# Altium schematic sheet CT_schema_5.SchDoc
size 304 x 172 mm
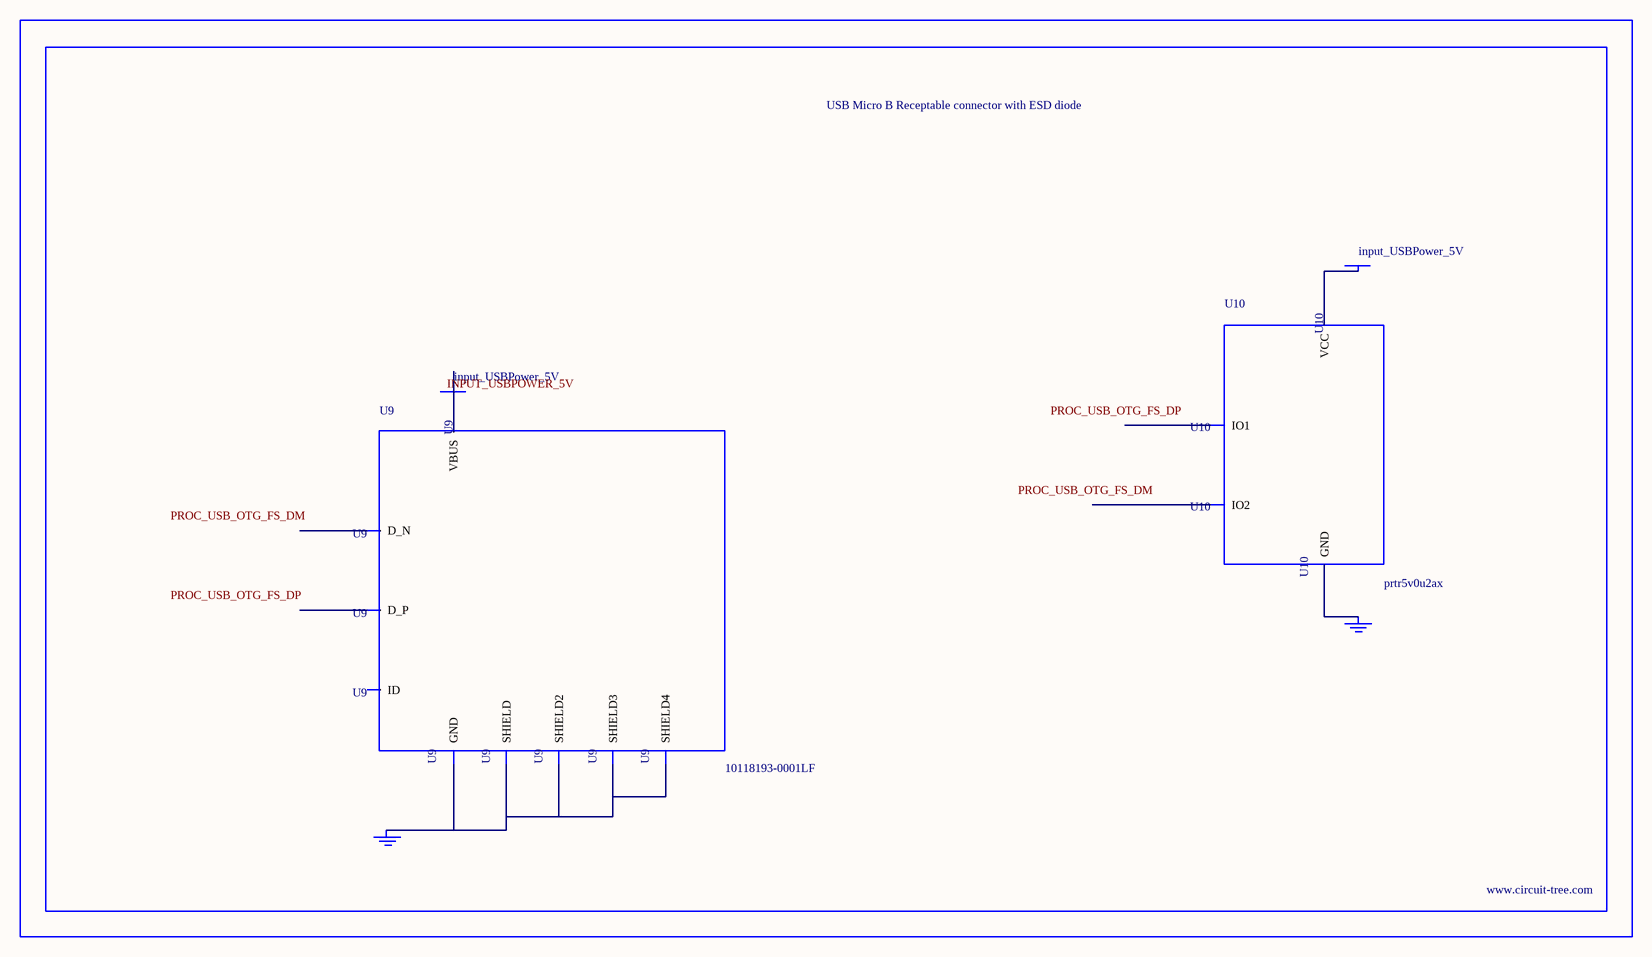
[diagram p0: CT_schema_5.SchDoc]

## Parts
BORDER4  (no value)
GND_INSTANCE_4_0  (no value)
GND_INSTANCE_4_1  (no value)
POWER_INSTANCE_4_0  input_USBPower_5V
POWER_INSTANCE_4_1  input_USBPower_5V
U9  10118193-0001LF  [FCI_10118193-0001LF]
U10  prtr5v0u2ax  [SOT143B]

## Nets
NetGND_INSTANCE_4_0_0: GND_INSTANCE_4_0.0(GND) U9.5(GND) U9.6(SHIELD) U9.7(SHIELD2) U9.8(SHIELD3) U9.9(SHIELD4)
NetGND_INSTANCE_4_1_0: GND_INSTANCE_4_1.0(GND) U10.1(GND)
NetPOWER_INSTANCE_4_0_0: POWER_INSTANCE_4_0.0(PWR) U9.1(VBUS)
NetPOWER_INSTANCE_4_1_0: POWER_INSTANCE_4_1.0(PWR) U10.4(VCC)

Not connected (* = marked no-connect by the designer): U9 2(D_N) 3(D_P) 4(ID); U10 2(IO1) 3(IO2)

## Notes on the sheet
- Labels drawn without touching a wire or pin: INPUT_USBPOWER_5V, PROC_USB_OTG_FS_DM, PROC_USB_OTG_FS_DP

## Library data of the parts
BORDER4 = BORDER_PAGE4
GND_INSTANCE_4_0 GND_INSTANCE_4_1 = GND
POWER_INSTANCE_4_0 POWER_INSTANCE_4_1 = PWR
